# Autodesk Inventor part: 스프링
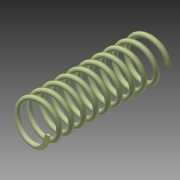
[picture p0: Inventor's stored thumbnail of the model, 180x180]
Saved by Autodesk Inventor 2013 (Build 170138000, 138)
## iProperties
Created: 2023-11
Part Number: 스프링
Material: 강철, 연강
Document SubType Name: Modeling
Designer: mdu-01
Density: 1 g/cm^3
Author: mdu-01
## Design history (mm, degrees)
sketch "스케치1" dims "d0" = 0.6
  geometry: L1 (0, 0)-(2.35, 0); L2 (2.35, 0)-(2.35, 16); L3 (2.35, 16)-(0, 16); L4 (0, 16)-(0, 0); L5 (-2.75, 16)-(2.75, 16) reference; L6 (2.65, 0)-(2.65, 6.462); 1 further point
  constraints: 10 end point, 2 parallel, 2 perpendicular, 1 coincident, 1 collinear, 1 horizontal, 1 horizontal alignment, 1 vertical, 2 other
  dimensions: "d2" = 16 distance between parallel lines of L1 L3 (derived); "d16" = 0.1 distance from line of L5.end L6
feature "코일1" sketch "스케치1" pitch "d3" = 10; turns "d5" = 10; dims "d4" = 16 (= d2), "d6" = 0, angle "d7" = 90 deg, angle "d8" = 90 deg, "d9" = 0, "d10" = 0
sketch "스케치2"
  geometry: L1 (-2.65, 0)-(-2.05, 0) reference; 1 further point
  constraints: 1 horizontal alignment
extrude "돌출1" cut sketch "스케치2" stored distance "d11" = 0; taper "d12" = 0 deg
node "작업 평면1"
sketch "스케치3"
  geometry: L1 (0.3, 0)-(-0.3, 0) reference; 1 further point
  constraints: 1 horizontal alignment
extrude "돌출2" cut sketch "스케치3" stored distance "d14" = 0; taper "d15" = 0 deg
node "솔리드1"
node "참조1"
node "절단 모서리 투영1"
node "절단 모서리 투영2"
other parameters: "d13" = 0
